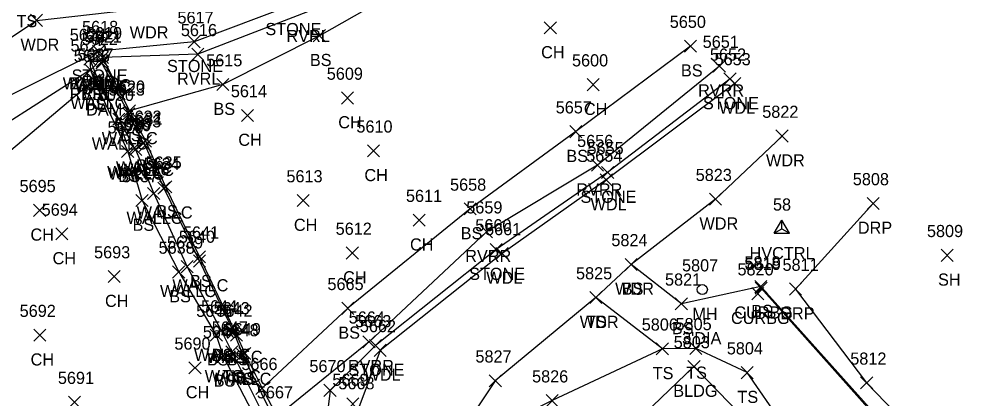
# Model space of a CAD drawing. Extents: x 1618146 to 1620418, y 640749 to 641927.
# Drawn here: x 1620082.5 to 1620241.1, y 641261.1 to 641323.6 of the extents above; entities that cross this region are included whole.
import ezdxf

# ---------------------------------------------------------------- set-up
doc = ezdxf.new("R2010")
doc.units = 0
for name, color, linetype in [('C_A', 7, 'Continuous'), ('C_I', 7, 'Continuous'), ('CPSM', 7, 'Continuous'), ('L_A', 7, 'Continuous'), ('L_C', 7, 'Continuous'), ('L_I', 7, 'Continuous'), ('L_TIC', 7, 'Continuous'), ('LASF', 7, 'Continuous'), ('LAWA', 7, 'Continuous'), ('LAWE', 7, 'Continuous'), ('LBC', 7, 'Continuous'), ('LELB', 7, 'Continuous'), ('LW', 7, 'Continuous'), ('R_A', 7, 'Continuous'), ('R_I', 7, 'Continuous'), ('R_TIC', 7, 'Continuous'), ('RC', 7, 'Continuous'), ('RDP', 7, 'Continuous'), ('U_A', 7, 'Continuous'), ('U_C', 7, 'Continuous'), ('U_I', 7, 'Continuous'), ('UUMH', 7, 'Continuous')]:
    doc.layers.add(name, color=color, linetype=linetype)

msp = doc.modelspace()

# ---------------------------------------------------------------- linework, layer by layer
at = {"layer": 'CPSM'}
for p, q in [((1620206.8, 641288.38), (1620208.05, 641290.54)), ((1620209.3, 641288.38), (1620208.05, 641290.54)), ((1620208.05, 641289.1), (1620208.05, 641290.54)), ((1620206.8, 641288.38), (1620208.05, 641289.1)), ((1620206.8, 641288.38), (1620209.3, 641288.38)), ((1620208.05, 641289.1), (1620208.05, 641289.1)), ((1620208.05, 641289.1), (1620209.3, 641288.38))]:
    msp.add_line(p, q, dxfattribs=at)
at = {"layer": 'L_TIC'}
for points in [[(1620084.38, 641322.43), (1620086.38, 641324.43)], [(1620086.38, 641322.43), (1620084.38, 641324.43)], [(1620168.94, 641321.19), (1620170.94, 641323.19)], [(1620170.94, 641321.19), (1620168.94, 641323.19)], [(1620130.93, 641319.91), (1620132.93, 641321.91)], [(1620132.93, 641319.91), (1620130.93, 641321.91)], [(1620110.32, 641318.92), (1620112.32, 641320.92)], [(1620112.32, 641318.92), (1620110.32, 641320.92)], [(1620192, 641318.19), (1620194, 641320.19)], [(1620194, 641318.19), (1620192, 641320.19)], [(1620094.61, 641317.35), (1620096.61, 641319.35)], [(1620096.61, 641317.35), (1620094.61, 641319.35)], [(1620095.25, 641316.33), (1620097.25, 641318.33)], [(1620097.25, 641316.33), (1620095.25, 641318.33)], [(1620095.25, 641316.33), (1620097.25, 641318.33)], [(1620097.25, 641316.33), (1620095.25, 641318.33)], [(1620110.93, 641316.84), (1620112.93, 641318.84)], [(1620112.93, 641316.84), (1620110.93, 641318.84)], [(1620093.16, 641316.06), (1620095.16, 641318.06)], [(1620095.16, 641316.06), (1620093.16, 641318.06)], [(1620093.16, 641316.06), (1620095.16, 641318.06)], [(1620095.16, 641316.06), (1620093.16, 641318.06)], [(1620095.14, 641315.39), (1620097.14, 641317.39)], [(1620097.14, 641315.39), (1620095.14, 641317.39)], [(1620095.2, 641315.75), (1620097.2, 641317.75)], [(1620097.2, 641315.75), (1620095.2, 641317.75)], [(1620095.2, 641315.75), (1620097.2, 641317.75)], [(1620097.2, 641315.75), (1620095.2, 641317.75)], [(1620196.76, 641314.89), (1620198.76, 641316.89)], [(1620198.76, 641314.89), (1620196.76, 641316.89)], [(1620093.28, 641314.29), (1620095.28, 641316.29)], [(1620095.28, 641314.29), (1620093.28, 641316.29)], [(1620093.28, 641314.29), (1620095.28, 641316.29)], [(1620095.28, 641314.29), (1620093.28, 641316.29)], [(1620093.86, 641312.59), (1620095.86, 641314.59)], [(1620095.86, 641312.59), (1620093.86, 641314.59)], [(1620093.86, 641312.59), (1620095.86, 641314.59)], [(1620095.86, 641312.59), (1620093.86, 641314.59)], [(1620094.4, 641312.81), (1620096.4, 641314.81)], [(1620096.4, 641312.81), (1620094.4, 641314.81)], [(1620115.04, 641311.86), (1620117.04, 641313.86)], [(1620117.04, 641311.86), (1620115.04, 641313.86)], [(1620175.98, 641311.85), (1620177.98, 641313.85)], [(1620177.98, 641311.85), (1620175.98, 641313.85)], [(1620198.52, 641312.8), (1620200.52, 641314.8)], [(1620200.52, 641312.8), (1620198.52, 641314.8)], [(1620199.29, 641312.04), (1620201.29, 641314.04)], [(1620201.29, 641312.04), (1620199.29, 641314.04)], [(1620135.55, 641309.65), (1620137.55, 641311.65)], [(1620137.55, 641309.65), (1620135.55, 641311.65)], [(1620099.57, 641307.04), (1620101.57, 641309.04)], [(1620101.57, 641307.04), (1620099.57, 641309.04)], [(1620099.67, 641307.52), (1620101.67, 641309.52)], [(1620101.67, 641307.52), (1620099.67, 641309.52)], [(1620099.67, 641307.52), (1620101.67, 641309.52)], [(1620101.67, 641307.52), (1620099.67, 641309.52)], [(1620119.1, 641306.77), (1620121.1, 641308.77)], [(1620121.1, 641306.77), (1620119.1, 641308.77)], [(1620097.93, 641306.16), (1620099.93, 641308.16)], [(1620099.93, 641306.16), (1620097.93, 641308.16)], [(1620173.14, 641304.11), (1620175.14, 641306.11)], [(1620175.14, 641304.11), (1620173.14, 641306.11)], [(1620101.91, 641302.23), (1620103.91, 641304.23)], [(1620103.91, 641302.23), (1620101.91, 641304.23)], [(1620102.32, 641302.57), (1620104.32, 641304.57)], [(1620104.32, 641302.57), (1620102.32, 641304.57)], [(1620207.08, 641303.38), (1620209.08, 641305.38)], [(1620209.08, 641303.38), (1620207.08, 641305.38)], [(1620099.39, 641300.82), (1620101.39, 641302.82)], [(1620101.39, 641300.82), (1620099.39, 641302.82)], [(1620100.47, 641301.42), (1620102.47, 641303.42)], [(1620102.47, 641301.42), (1620100.47, 641303.42)], [(1620100.69, 641301.19), (1620102.69, 641303.19)], [(1620102.69, 641301.19), (1620100.69, 641303.19)], [(1620102.26, 641301.81), (1620104.26, 641303.81)], [(1620104.26, 641301.81), (1620102.26, 641303.81)], [(1620139.85, 641300.95), (1620141.85, 641302.95)], [(1620141.85, 641300.95), (1620139.85, 641302.95)], [(1620176.71, 641298.58), (1620178.71, 641300.58)], [(1620178.71, 641298.58), (1620176.71, 641300.58)], [(1620178.37, 641297.38), (1620180.37, 641299.38)], [(1620180.37, 641297.38), (1620178.37, 641299.38)], [(1620178.16, 641296.15), (1620180.16, 641298.15)], [(1620180.16, 641296.15), (1620178.16, 641298.15)], [(1620105.32, 641294.8), (1620107.32, 641296.8)], [(1620107.32, 641294.8), (1620105.32, 641296.8)], [(1620105.62, 641295.02), (1620107.62, 641297.02)], [(1620107.62, 641295.02), (1620105.62, 641297.02)], [(1620101.74, 641292.77), (1620103.74, 641294.77)], [(1620103.74, 641292.77), (1620101.74, 641294.77)], [(1620103.66, 641293.91), (1620105.66, 641295.91)], [(1620105.66, 641293.91), (1620103.66, 641295.91)], [(1620128.25, 641292.76), (1620130.25, 641294.76)], [(1620130.25, 641292.76), (1620128.25, 641294.76)], [(1620196.13, 641292.98), (1620198.13, 641294.98)], [(1620198.13, 641292.98), (1620196.13, 641294.98)], [(1620084.89, 641291.15), (1620086.89, 641293.15)], [(1620086.89, 641291.15), (1620084.89, 641293.15)], [(1620155.75, 641291.38), (1620157.75, 641293.38)], [(1620157.75, 641291.38), (1620155.75, 641293.38)], [(1620147.36, 641289.53), (1620149.36, 641291.53)], [(1620149.36, 641289.53), (1620147.36, 641291.53)], [(1620088.53, 641287.26), (1620090.53, 641289.26)], [(1620090.53, 641287.26), (1620088.53, 641289.26)], [(1620158.43, 641287.63), (1620160.43, 641289.63)], [(1620160.43, 641287.63), (1620158.43, 641289.63)], [(1620160.04, 641284.69), (1620162.04, 641286.69)], [(1620162.04, 641284.69), (1620160.04, 641286.69)], [(1620111.21, 641283.5), (1620113.21, 641285.5)], [(1620113.21, 641283.5), (1620111.21, 641285.5)], [(1620136.35, 641284.12), (1620138.35, 641286.12)], [(1620138.35, 641284.12), (1620136.35, 641286.12)], [(1620160.99, 641284.05), (1620162.99, 641286.05)], [(1620162.99, 641284.05), (1620160.99, 641286.05)], [(1620234.27, 641283.74), (1620236.27, 641285.74)], [(1620236.27, 641283.74), (1620234.27, 641285.74)], [(1620109.17, 641281.86), (1620111.17, 641283.86)], [(1620111.17, 641281.86), (1620109.17, 641283.86)], [(1620111.2, 641282.8), (1620113.2, 641284.8)], [(1620113.2, 641282.8), (1620111.2, 641284.8)], [(1620182.25, 641282.24), (1620184.25, 641284.24)], [(1620184.25, 641282.24), (1620182.25, 641284.24)], [(1620182.25, 641282.24), (1620184.25, 641284.24)], [(1620184.25, 641282.24), (1620182.25, 641284.24)], [(1620097.16, 641280.24), (1620099.16, 641282.24)], [(1620099.16, 641280.24), (1620097.16, 641282.24)], [(1620107.78, 641281), (1620109.78, 641283)], [(1620109.78, 641281), (1620107.78, 641283)], [(1620203.58, 641278.58), (1620205.58, 641280.58)], [(1620205.58, 641278.58), (1620203.58, 641280.58)], [(1620176.43, 641276.78), (1620178.43, 641278.78)], [(1620178.43, 641276.78), (1620176.43, 641278.78)], [(1620176.43, 641276.78), (1620178.43, 641278.78)], [(1620178.43, 641276.78), (1620176.43, 641278.78)], [(1620135.61, 641275.01), (1620137.61, 641277.01)], [(1620137.61, 641275.01), (1620135.61, 641277.01)], [(1620190.51, 641275.75), (1620192.51, 641277.75)], [(1620192.51, 641275.75), (1620190.51, 641277.75)], [(1620084.91, 641270.59), (1620086.91, 641272.59)], [(1620086.91, 641270.59), (1620084.91, 641272.59)], [(1620113.97, 641270.6), (1620115.97, 641272.6)], [(1620115.97, 641270.6), (1620113.97, 641272.6)], [(1620114.77, 641271.34), (1620116.77, 641273.34)], [(1620116.77, 641271.34), (1620114.77, 641273.34)], [(1620114.77, 641271.34), (1620116.77, 641273.34)], [(1620116.77, 641271.34), (1620114.77, 641273.34)], [(1620116.83, 641271.03), (1620118.83, 641273.03)], [(1620118.83, 641271.03), (1620116.83, 641273.03)], [(1620116.83, 641271.03), (1620118.83, 641273.03)], [(1620118.83, 641271.03), (1620116.83, 641273.03)], [(1620117.29, 641270.62), (1620119.29, 641272.62)], [(1620119.29, 641270.62), (1620117.29, 641272.62)], [(1620139.11, 641269.5), (1620141.11, 641271.5)], [(1620141.11, 641269.5), (1620139.11, 641271.5)], [(1620140.17, 641268.89), (1620142.17, 641270.89)], [(1620142.17, 641268.89), (1620140.17, 641270.89)], [(1620115.11, 641267.12), (1620117.11, 641269.12)], [(1620117.11, 641267.12), (1620115.11, 641269.12)], [(1620116.53, 641267.84), (1620118.53, 641269.84)], [(1620118.53, 641267.84), (1620116.53, 641269.84)], [(1620116.53, 641267.84), (1620118.53, 641269.84)], [(1620118.53, 641267.84), (1620116.53, 641269.84)], [(1620118.28, 641267.4), (1620120.28, 641269.4)], [(1620120.28, 641267.4), (1620118.28, 641269.4)], [(1620118.28, 641267.4), (1620120.28, 641269.4)], [(1620120.28, 641267.4), (1620118.28, 641269.4)], [(1620118.66, 641267.58), (1620120.66, 641269.58)], [(1620120.66, 641267.58), (1620118.66, 641269.58)], [(1620140.95, 641268.08), (1620142.95, 641270.08)], [(1620142.95, 641268.08), (1620140.95, 641270.08)], [(1620187.38, 641268.34), (1620189.38, 641270.34)], [(1620189.38, 641268.34), (1620187.38, 641270.34)], [(1620187.38, 641268.34), (1620189.38, 641270.34)], [(1620189.38, 641268.34), (1620187.38, 641270.34)], [(1620192.89, 641268.41), (1620194.89, 641270.41)], [(1620194.89, 641268.41), (1620192.89, 641270.41)], [(1620110.47, 641265.2), (1620112.47, 641267.2)], [(1620112.47, 641265.2), (1620110.47, 641267.2)], [(1620192.59, 641265.43), (1620194.59, 641267.43)], [(1620194.59, 641265.43), (1620192.59, 641267.43)], [(1620192.59, 641265.43), (1620194.59, 641267.43)], [(1620194.59, 641265.43), (1620192.59, 641267.43)], [(1620201.33, 641264.42), (1620203.33, 641266.42)], [(1620203.33, 641264.42), (1620201.33, 641266.42)], [(1620159.88, 641263.08), (1620161.88, 641265.08)], [(1620161.88, 641263.08), (1620159.88, 641265.08)], [(1620121.5, 641261.84), (1620123.5, 641263.84)], [(1620123.5, 641261.84), (1620121.5, 641263.84)], [(1620121.5, 641261.84), (1620123.5, 641263.84)], [(1620123.5, 641261.84), (1620121.5, 641263.84)], [(1620132.69, 641261.49), (1620134.69, 641263.49)], [(1620134.69, 641261.49), (1620132.69, 641263.49)], [(1620090.63, 641259.55), (1620092.63, 641261.55)], [(1620092.63, 641259.55), (1620090.63, 641261.55)], [(1620136.43, 641259.24), (1620138.43, 641261.24)], [(1620138.43, 641259.24), (1620136.43, 641261.24)], [(1620169.25, 641259.8), (1620171.25, 641261.8)], [(1620171.25, 641259.8), (1620169.25, 641261.8)]]:
    msp.add_lwpolyline(points, dxfattribs=at)
at = {"layer": 'LASF'}
for points in [[(1620170.67, 641357.92), (1620151.16, 641340.42), (1620127.51, 641326), (1620111.32, 641319.92), (1620095.61, 641318.35), (1620069.66, 641305.45), (1620049.44, 641298.08), (1620030.95, 641301.74), (1620009.21, 641303.41), (1619992.86, 641294.85), (1619980.43, 641291.88)], [(1620199.52, 641313.8), (1620179.37, 641298.38), (1620161.04, 641285.69), (1620141.17, 641269.89), (1620133.69, 641262.49), (1620132.65, 641253.95), (1620128.76, 641249.51), (1620128.68, 641249.15), (1620127.84, 641248.2), (1620126.92, 641247.39), (1620116.78, 641233.91), (1620111.43, 641226.04)]]:
    msp.add_lwpolyline(points, dxfattribs=at)
at = {"layer": 'LAWA'}
for points in [[(1620069.66, 641305.45), (1620057.71, 641308.73), (1620064.58, 641309.15), (1620072.37, 641314.79), (1620085.38, 641323.43), (1620103.34, 641325.45), (1620118.56, 641334.23), (1620140.8, 641343.73), (1620160.99, 641362.12)], [(1620200.29, 641313.04), (1620179.16, 641297.15), (1620161.99, 641285.05), (1620141.95, 641269.08), (1620138.41, 641259.67)], [(1620208.08, 641304.38), (1620197.13, 641293.98), (1620183.25, 641283.24), (1620177.43, 641277.78), (1620160.88, 641264.08), (1620152.96, 641252.21), (1620140.67, 641237.05), (1620134.78, 641235.24)]]:
    msp.add_lwpolyline(points, dxfattribs=at)
at = {"layer": 'LAWE'}
for points in [[(1620171.86, 641355.85), (1620152.34, 641338.2), (1620129.96, 641324.85), (1620111.93, 641317.84), (1620096.25, 641317.33), (1620096.2, 641316.75), (1620094.16, 641317.06), (1620094.28, 641315.29), (1620071.24, 641300.59), (1620050.39, 641293.63), (1620030.98, 641297.72), (1620009.6, 641296.43), (1619997.99, 641289.69), (1619969.13, 641278.68), (1619952.14, 641274.33), (1619935.16, 641265.54), (1619913.67, 641252.74)], [(1620197.76, 641315.89), (1620177.71, 641299.58), (1620159.43, 641288.63), (1620140.11, 641270.5), (1620125, 641258.18)]]:
    msp.add_lwpolyline(points, dxfattribs=at)
at = {"layer": 'LBC'}
for points in [[(1620215.06, 641244.3), (1620205.98, 641235.71), (1620202.68, 641232.58), (1620189.5, 641220.11), (1620199.08, 641211.83), (1620201.42, 641213.81), (1620202.47, 641212.52), (1620205.83, 641209.33), (1620206.94, 641208.23), (1620204.76, 641205.9), (1620213.69, 641196.39), (1620197.14, 641180.51), (1620189.98, 641173.97), (1620166.56, 641198.69), (1620162.72, 641202.83), (1620152.84, 641213.23), (1620141.67, 641224.9), (1620165.02, 641247.38), (1620169.21, 641243.06), (1620193.59, 641266.43)], [(1620215.06, 641244.3), (1620193.59, 641266.43)]]:
    msp.add_lwpolyline(points, dxfattribs=at)
at = {"layer": 'LELB'}
for points in [[(1620178.37, 641350.58), (1620156.78, 641335.03), (1620131.93, 641320.91), (1620116.04, 641312.86), (1620100.67, 641308.52)], [(1620193, 641319.19), (1620174.14, 641305.11), (1620156.75, 641292.38), (1620136.61, 641276.01), (1620122.5, 641262.84)], [(1620096.25, 641317.33), (1620100.67, 641308.52), (1620103.32, 641303.57), (1620106.62, 641296.02), (1620112.21, 641284.5), (1620118.29, 641271.62), (1620119.66, 641268.58), (1620122.5, 641262.84), (1620125, 641258.18), (1620128.76, 641249.51)], [(1620094.28, 641315.29), (1620094.86, 641313.59), (1620100.39, 641301.82), (1620102.74, 641293.77), (1620108.78, 641282), (1620114.97, 641271.6), (1620116.11, 641268.12), (1620126.92, 641247.39)], [(1620094.86, 641313.59), (1620072.65, 641294.84), (1620058.23, 641288.21), (1620031.72, 641288.47), (1620010.9, 641284.85), (1620001.9, 641278.17), (1619970.88, 641271.33), (1619953.58, 641271.43), (1619935.99, 641263.46), (1619914.63, 641250.92)], [(1620227.8, 641252.25), (1620229.01, 641252.32), (1620204.58, 641279.58), (1620191.51, 641276.75), (1620183.25, 641283.24)], [(1620188.38, 641269.34), (1620177.43, 641277.78)], [(1620117.83, 641272.03), (1620115.77, 641272.34)], [(1620214.97, 641229.37), (1620217.37, 641235.3), (1620219.62, 641240.43), (1620202.33, 641265.42), (1620193.89, 641269.41), (1620188.38, 641269.34), (1620170.25, 641260.8), (1620152.96, 641252.21)], [(1620117.53, 641268.84), (1620119.28, 641268.4)]]:
    msp.add_lwpolyline(points, dxfattribs=at)
at = {"layer": 'LW'}
for points in [[(1620094.16, 641317.06), (1620095.4, 641313.81), (1620098.93, 641307.16), (1620101.47, 641302.42), (1620101.69, 641302.19), (1620104.66, 641294.91), (1620110.17, 641282.86), (1620115.77, 641272.34), (1620117.53, 641268.84), (1620127.84, 641248.2)], [(1620096.2, 641316.75), (1620096.14, 641316.39), (1620100.57, 641308.04), (1620102.91, 641303.23), (1620103.26, 641302.81), (1620106.32, 641295.8), (1620112.2, 641283.8), (1620117.83, 641272.03), (1620119.28, 641268.4), (1620128.68, 641249.15)]]:
    msp.add_lwpolyline(points, dxfattribs=at)
at = {"layer": 'R_TIC'}
for points in [[(1620222.07, 641292.28), (1620224.07, 641294.28)], [(1620224.07, 641292.28), (1620222.07, 641294.28)], [(1620203.65, 641278.32), (1620205.65, 641280.32)], [(1620205.65, 641278.32), (1620203.65, 641280.32)], [(1620209.29, 641278.18), (1620211.29, 641280.18)], [(1620211.29, 641278.18), (1620209.29, 641280.18)], [(1620203.1, 641277.43), (1620205.1, 641279.43)], [(1620205.1, 641277.43), (1620203.1, 641279.43)], [(1620221, 641262.73), (1620223, 641264.73)], [(1620223, 641262.73), (1620221, 641264.73)]]:
    msp.add_lwpolyline(points, dxfattribs=at)
at = {"layer": 'RC'}
msp.add_lwpolyline([(1620227.8, 641252.25), (1620228.45, 641252.57), (1620204.65, 641279.32), (1620204.1, 641278.43)], dxfattribs=at)
at = {"layer": 'RDP'}
msp.add_lwpolyline([(1620223.07, 641293.28), (1620210.29, 641279.18), (1620222, 641263.73), (1620237.69, 641247.5), (1620241.11, 641244.16)], dxfattribs=at)
at = {"layer": 'UUMH'}
for p, q in [((1620194.96, 641279.09), (1620194.96, 641279.09)), ((1620195.79, 641279.09), (1620195.79, 641279.09))]:
    msp.add_line(p, q, dxfattribs=at)
msp.add_circle((1620194.96, 641279.09), 0.833, dxfattribs=at)

# ---------------------------------------------------------------- texts
at = {"layer": 'C_A'}
msp.add_text('HVCTRL', height=2, dxfattribs=at).set_placement((1620202.74, 641284.1))
at = {"layer": 'C_I'}
msp.add_text('58', height=2, dxfattribs=at).set_placement((1620206.59, 641292.1))
at = {"layer": 'L_A'}
for s, p in [('TS', (1620082.08, 641322.31)), ('STONE', (1620123.05, 641321)), ('WDR', (1620100.71, 641320.45)), ('RVRL', (1620126.52, 641319.85)), ('WDR', (1620082.74, 641318.43)), ('CH', (1620168.43, 641317.19)), ('STONE', (1620106.86, 641314.92)), ('BS', (1620130.37, 641315.91)), ('STONE', (1620091.15, 641313.35)), ('BS', (1620191.44, 641314.19)), ('WALLC', (1620089.69, 641312.06)), ('RVRL', (1620090.73, 641312.06)), ('WALLC', (1620091.74, 641311.75)), ('RVRL', (1620092.77, 641311.75)), ('RVRL', (1620092.82, 641312.33)), ('BS', (1620094.69, 641312.33)), ('RVRL', (1620108.5, 641312.84)), ('RVRL', (1620090.85, 641310.29)), ('WALLC', (1620091.68, 641311.39)), ('BS', (1620092.72, 641310.29)), ('RVRR', (1620194.27, 641310.89)), ('WALLC', (1620090.94, 641308.81)), ('BS', (1620093.3, 641308.59)), ('BS', (1620093.3, 641308.59)), ('STONE', (1620195.06, 641308.8)), ('BS', (1620114.49, 641307.86)), ('CH', (1620175.47, 641307.85)), ('WDL', (1620197.71, 641308.04)), ('CH', (1620135.04, 641305.65)), ('BS', (1620099.12, 641303.52)), ('BS', (1620099.12, 641303.52)), ('WALLC', (1620094.47, 641302.16)), ('WALLC', (1620096.11, 641303.04)), ('CH', (1620118.59, 641302.77)), ('BS', (1620172.58, 641300.11)), ('WDR', (1620205.44, 641299.38)), ('WALLC', (1620097, 641297.42)), ('WALLC', (1620097.22, 641297.19)), ('WALLC', (1620098.44, 641298.23)), ('WALLC', (1620098.79, 641297.81)), ('BS', (1620101.76, 641298.57)), ('BS', (1620098.83, 641296.82)), ('CH', (1620139.34, 641296.95)), ('RVRR', (1620174.22, 641294.58)), ('STONE', (1620174.91, 641293.38)), ('BS', (1620105.06, 641291.02)), ('WDL', (1620176.57, 641292.15)), ('WALLC', (1620100.19, 641289.91)), ('WALLC', (1620101.86, 641290.8)), ('BS', (1620101.18, 641288.77)), ('CH', (1620127.74, 641288.76)), ('WDR', (1620194.49, 641288.98)), ('CH', (1620084.38, 641287.15)), ('BS', (1620155.19, 641287.38)), ('CH', (1620146.85, 641285.53)), ('CH', (1620088.02, 641283.26)), ('RVRR', (1620155.94, 641283.63)), ('CH', (1620135.84, 641280.12)), ('STONE', (1620156.58, 641280.69)), ('WDL', (1620159.41, 641280.05)), ('SH', (1620233.76, 641279.74)), ('WALLC', (1620107.74, 641278.8)), ('BS', (1620110.65, 641279.5)), ('WDR', (1620180.61, 641278.24)), ('BS', (1620181.69, 641278.24)), ('WALLC', (1620105.7, 641277.86)), ('BS', (1620107.22, 641277)), ('CH', (1620096.65, 641276.24)), ('BS', (1620203.02, 641274.58)), ('WDR', (1620174.79, 641272.78)), ('TS', (1620175.84, 641272.78)), ('BS', (1620135.05, 641271.01)), ('BS', (1620189.95, 641271.75)), ('WALLC', (1620111.3, 641267.34)), ('WALLC', (1620113.37, 641267.03)), ('BS', (1620114.21, 641267.34)), ('BS', (1620116.27, 641267.03)), ('CH', (1620084.4, 641266.59)), ('BS', (1620113.41, 641266.6)), ('BS', (1620116.73, 641266.62)), ('RVRR', (1620136.62, 641265.5)), ('STONE', (1620136.72, 641264.89)), ('WDL', (1620139.36, 641264.08)), ('TS', (1620186.79, 641264.34)), ('TS', (1620186.79, 641264.34)), ('TS', (1620192.3, 641264.41)), ('WALLC', (1620113.06, 641263.84)), ('BS', (1620114.55, 641263.12)), ('WALLC', (1620114.82, 641263.4)), ('TS', (1620115.94, 641263.84)), ('TS', (1620117.69, 641263.4)), ('BS', (1620118.1, 641263.58)), ('CH', (1620109.95, 641261.2)), ('BLDG', (1620190.18, 641261.43)), ('BLDG', (1620190.18, 641261.43)), ('TS', (1620200.74, 641260.42))]:
    msp.add_text(s, height=2, dxfattribs=at).set_placement(p)
at = {"layer": 'L_C'}
msp.add_text('DAM', height=2, dxfattribs=at).set_placement((1620093.54, 641307.75))
at = {"layer": 'L_I'}
for s, p in [('5617', (1620108.58, 641322.92)), ('5618', (1620092.87, 641321.35)), ('5650', (1620189.6, 641322.19)), ('5624', (1620090.85, 641320.06)), ('5624', (1620090.85, 641320.06)), ('5622', (1620092.83, 641319.39)), ('5621', (1620093.46, 641319.75)), ('5621', (1620093.46, 641319.75)), ('5619', (1620093.51, 641320.33)), ('5619', (1620093.51, 641320.33)), ('5616', (1620109.13, 641320.84)), ('5625', (1620090.97, 641318.29)), ('5625', (1620090.97, 641318.29)), ('5651', (1620195.02, 641318.89)), ('5626', (1620091.5, 641316.59)), ('5626', (1620091.5, 641316.59)), ('5627', (1620092.1, 641316.81)), ('5652', (1620196.21, 641316.8)), ('5615', (1620113.3, 641315.86)), ('5600', (1620173.51, 641315.85)), ('5653', (1620196.98, 641316.04)), ('5609', (1620133.15, 641313.65)), ('5620', (1620097.28, 641311.52)), ('5620', (1620097.28, 641311.52)), ('6090', (1620095.46, 641310.16)), ('5623', (1620097.26, 641311.04)), ('5614', (1620117.36, 641310.77)), ('5657', (1620170.83, 641308.11)), ('5822', (1620204.82, 641307.38)), ('5628', (1620098.16, 641305.42)), ('5630', (1620098.29, 641305.19)), ('5633', (1620099.95, 641305.81)), ('5632', (1620100.01, 641306.57)), ('5631', (1620100.17, 641306.23)), ('5629', (1620097.07, 641304.82)), ('5610', (1620138.02, 641304.95)), ('5656', (1620174.35, 641302.58)), ('5655', (1620176.06, 641301.38)), ('5634', (1620103.01, 641298.8)), ('5635', (1620103.32, 641299.02)), ('5654', (1620175.85, 641300.15)), ('5636', (1620101.3, 641297.91)), ('5637', (1620099.44, 641296.77)), ('5613', (1620126.51, 641296.76)), ('5823', (1620193.87, 641296.98)), ('5695', (1620082.58, 641295.15)), ('5658', (1620153.44, 641295.38)), ('5611', (1620146.18, 641293.53)), ('5694', (1620086.22, 641291.26)), ('5659', (1620156.11, 641291.63)), ('5612', (1620134.61, 641288.12)), ('5660', (1620157.59, 641288.69)), ('5661', (1620159.2, 641288.05)), ('5809', (1620231.93, 641287.74)), ('5640', (1620108.81, 641286.8)), ('5641', (1620109.47, 641287.5)), ('5824', (1620179.99, 641286.24)), ('5824', (1620179.99, 641286.24)), ('5638', (1620105.47, 641285)), ('5639', (1620106.85, 641285.86)), ('5693', (1620094.85, 641284.24)), ('5818', (1620201.88, 641282.58)), ('5825', (1620174.17, 641280.78)), ('5825', (1620174.17, 641280.78)), ('5821', (1620188.82, 641279.75)), ('5665', (1620133.26, 641279.01)), ('5644', (1620112.46, 641275.34)), ('5644', (1620112.46, 641275.34)), ('5643', (1620114.52, 641275.03)), ('5643', (1620114.52, 641275.03)), ('5692', (1620082.6, 641274.59)), ('5645', (1620111.66, 641274.6)), ('5642', (1620114.98, 641274.62)), ('5664', (1620136.76, 641273.5)), ('5647', (1620114.22, 641271.84)), ('5647', (1620114.22, 641271.84)), ('5663', (1620137.82, 641272.89)), ('5662', (1620138.59, 641272.08)), ('5806', (1620184.99, 641272.34)), ('5806', (1620184.99, 641272.34)), ('5805', (1620190.55, 641272.41)), ('5646', (1620112.75, 641271.12)), ('5648', (1620115.98, 641271.4)), ('5648', (1620115.98, 641271.4)), ('5649', (1620116.35, 641271.58)), ('5690', (1620108.07, 641269.2)), ('5803', (1620190.25, 641269.43)), ('5803', (1620190.25, 641269.43)), ('5827', (1620157.62, 641267.08)), ('5804', (1620198.99, 641268.42)), ('5666', (1620119.09, 641265.84)), ('5666', (1620119.09, 641265.84)), ('5670', (1620130.29, 641265.49)), ('5691', (1620088.89, 641263.55)), ('5669', (1620134.07, 641263.24)), ('5668', (1620135.06, 641262.67)), ('5668', (1620135.06, 641262.67)), ('5668', (1620135.06, 641262.67)), ('5826', (1620166.94, 641263.8)), ('5667', (1620121.64, 641261.18)), ('5667', (1620121.64, 641261.18))]:
    msp.add_text(s, height=2, dxfattribs=at).set_placement(p)
at = {"layer": 'R_A'}
for s, p in [('DRP', (1620220.56, 641288.28)), ('CURBG', (1620199.68, 641273.43)), ('CURBG', (1620200.23, 641274.32)), ('DRP', (1620207.78, 641274.18))]:
    msp.add_text(s, height=2, dxfattribs=at).set_placement(p)
at = {"layer": 'R_I'}
for s, p in [('5808', (1620219.73, 641296.28)), ('5820', (1620200.75, 641281.43)), ('5819', (1620201.95, 641282.32)), ('5811', (1620208.16, 641282.18)), ('5812', (1620219.31, 641266.73))]:
    msp.add_text(s, height=2, dxfattribs=at).set_placement(p)
at = {"layer": 'U_A'}
msp.add_text('MH', height=2, dxfattribs=at).set_placement((1620193.32, 641274.09))
at = {"layer": 'U_C'}
msp.add_text("3'DIA", height=2, dxfattribs=at).set_placement((1620191.64, 641270.09))
at = {"layer": 'U_I'}
msp.add_text('5807', height=2, dxfattribs=at).set_placement((1620191.62, 641282.09))

doc.saveas('drawing.dxf')
